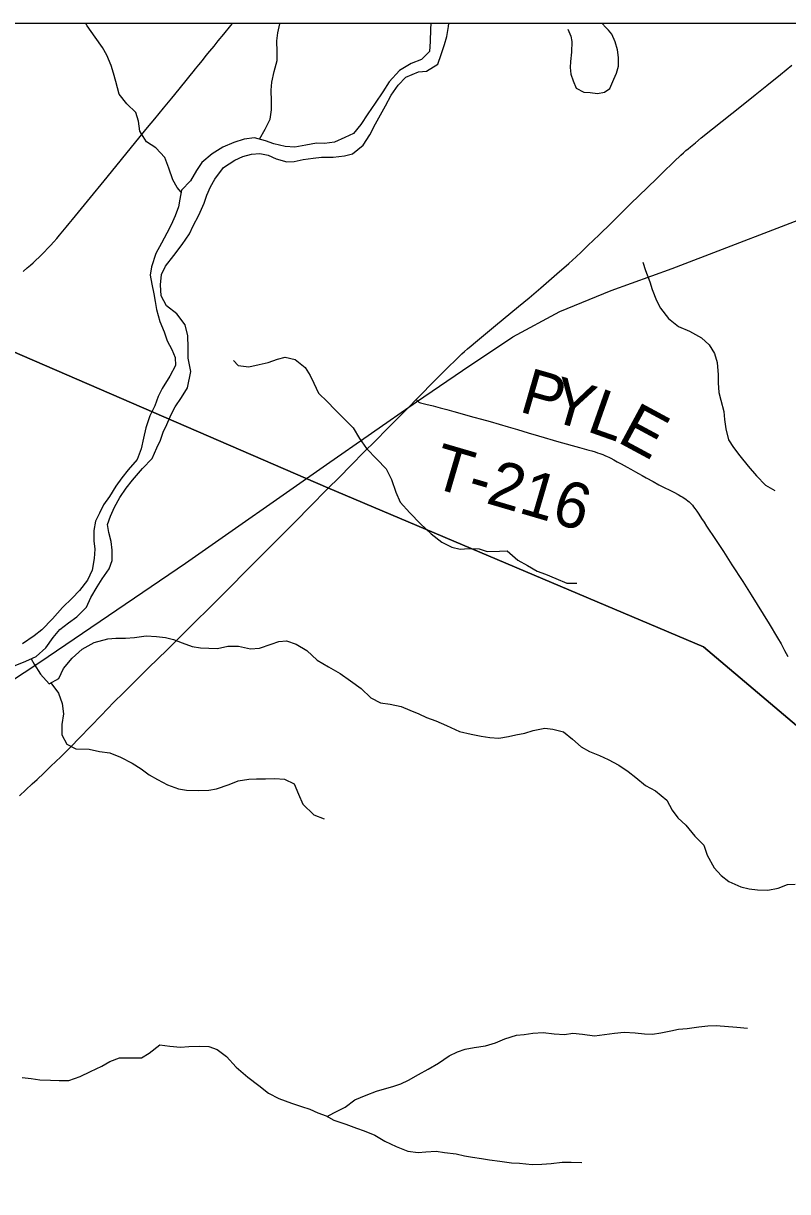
# Model space of a CAD drawing. Extents: x 0 to 34, y 0 to 22.
# Drawn here: x 20.142 to 21.094, y 19.65 to 21.106 of the extents above; entities that cross this region are included whole.
import ezdxf

# ---------------------------------------------------------------- set-up
doc = ezdxf.new("R2010")
doc.units = 0
for name, color, linetype in [('GM_X_Corporation', 7, 'Continuous'), ('GM_X_County_Road', 7, 'Continuous'), ('GM_X_Major_River', 7, 'Continuous'), ('GM_X_Minor_Lake', 7, 'Continuous'), ('GM_X_Minor_River', 7, 'Continuous'), ('GM_X_Rail_Line', 7, 'Continuous'), ('GM_X_Township_Road', 7, 'Continuous'), ('GM_X_Township_Road_Text', 7, 'Continuous')]:
    doc.layers.add(name, color=color, linetype=linetype)

msp = doc.modelspace()

# ---------------------------------------------------------------- linework, layer by layer
at = {"layer": 'GM_X_Corporation'}
for points in [[(17.597, 14.3059), (23.9625, 14.3059), (23.9625, 21.1059), (18.23, 21.1059), (18.203, 20.7746), (18.1731, 20.4696), (18.0879, 19.5959), (18.0387, 19.0962), (17.9672, 18.2605), (17.8718, 17.2256), (17.7834, 16.317), (17.7373, 15.7617), (17.7239, 15.6245), (17.6136, 14.4601)], [(23.8219, 21.1059), (19.1325, 21.1059), (19.4417, 20.9771), (20.0591, 20.7271), (20.5209, 20.5272), (20.9887, 20.3291), (21.1503, 20.1924), (21.2024, 20.1483), (21.462, 19.9289), (21.6862, 19.7442), (22.4736, 19.0897), (22.5453, 19.0171), (22.8523, 19.0143), (22.8728, 18.8666), (23.8372, 18.7818), (23.8567, 18.7798), (23.8401, 19.9225), (23.83, 20.7057)]]:
    msp.add_lwpolyline(points, close=True, dxfattribs=at)
msp.add_lwpolyline([(22.4736, 19.0897), (21.6862, 19.7442), (21.462, 19.9289), (21.2024, 20.1483), (21.1503, 20.1924), (20.9887, 20.3291), (20.5209, 20.5272), (20.0591, 20.7271), (19.4417, 20.9771), (19.1325, 21.1059), (18.23, 21.1059), (18.203, 20.7746), (18.1731, 20.4696), (18.0879, 19.5959), (18.0387, 19.0962), (17.9672, 18.2605), (17.8718, 17.2256), (17.7834, 16.317)], dxfattribs=at)
at = {"layer": 'GM_X_County_Road'}
for points in [[(20.1413, 20.7967), (20.1463, 20.8011), (20.1503, 20.8047), (20.1536, 20.8076), (20.1571, 20.8108), (20.1611, 20.8146), (20.1647, 20.8181), (20.168, 20.8214), (20.1718, 20.8254), (20.1755, 20.8293), (20.1795, 20.8337), (20.1831, 20.8378), (20.1867, 20.8421), (20.1909, 20.8471), (20.1949, 20.8519), (20.1988, 20.8566), (20.2029, 20.8616), (20.2216, 20.8845), (20.2459, 20.9143), (20.2637, 20.9361), (20.2872, 20.9651), (20.2962, 20.9761), (20.3052, 20.987), (20.3162, 21.0003), (20.3265, 21.0127), (20.3357, 21.024), (20.3461, 21.0368), (20.3495, 21.0411), (20.3529, 21.0454), (20.3561, 21.0493), (20.3602, 21.0544), (20.3647, 21.0598), (20.3694, 21.0657), (20.374, 21.0713), (20.3791, 21.0776), (20.3843, 21.0839), (20.3914, 21.0925), (20.4, 21.1033), (20.4021, 21.1059)], [(20.6307, 20.6371), (20.6375, 20.644), (20.65, 20.6566), (20.6609, 20.6675), (20.6696, 20.6761), (20.6814, 20.6878), (20.6878, 20.694), (20.6912, 20.6971), (20.695, 20.7005), (20.6993, 20.7042), (20.7047, 20.7087), (20.7296, 20.7294), (20.7583, 20.7531), (20.7716, 20.764), (20.7861, 20.7763), (20.8063, 20.7938), (20.821, 20.8068), (20.83, 20.815), (20.8364, 20.8208), (20.8445, 20.8285), (20.8524, 20.8362), (20.8583, 20.842), (20.874, 20.8575), (20.8857, 20.8689), (20.8984, 20.8813), (20.9082, 20.8908), (20.9302, 20.9123), (20.9423, 20.9242), (20.9476, 20.9294), (20.9521, 20.9339), (20.9604, 20.9415), (20.9639, 20.9446), (20.9669, 20.9473), (20.9696, 20.9496), (20.9726, 20.9522), (20.9787, 20.9571), (20.9861, 20.9631), (21, 20.9743), (21.0362, 21.0033), (21.0531, 21.0167), (21.0679, 21.0286), (21.0848, 21.0422), (21.099, 21.0536)], [(20.5211, 20.5266), (20.5344, 20.5398), (20.5502, 20.5557), (20.5658, 20.5715), (20.5803, 20.5859), (20.5948, 20.6005), (20.6031, 20.6089), (20.6146, 20.6207), (20.6224, 20.6286), (20.6307, 20.6371)], [(20.1367, 20.1433), (20.1527, 20.1583), (20.1586, 20.1639), (20.1669, 20.1717), (20.1749, 20.1794), (20.1828, 20.187), (20.1873, 20.1914), (20.1943, 20.1982), (20.201, 20.2049), (20.2111, 20.2152), (20.2256, 20.2302), (20.2386, 20.2436), (20.2544, 20.26), (20.2663, 20.2719), (20.2782, 20.284), (20.2975, 20.3028), (20.3208, 20.3255), (20.3406, 20.3451), (20.3578, 20.3623), (20.3705, 20.3749), (20.3829, 20.3872), (20.3925, 20.3969), (20.4011, 20.4056), (20.4162, 20.4207), (20.4437, 20.4484), (20.4819, 20.4867), (20.4978, 20.5027), (20.5211, 20.5266)]]:
    msp.add_lwpolyline(points, dxfattribs=at)
at = {"layer": 'GM_X_Major_River'}
msp.add_line((20.3503, 20.6722), (20.3467, 20.6886), dxfattribs=at)
for points in [[(20.6491, 21.1059), (20.6486, 21.0988), (20.6485, 21.0832), (20.6474, 21.0707), (20.6376, 21.0608), (20.6246, 21.0558), (20.61, 21.0471), (20.5971, 21.033), (20.5892, 21.0207), (20.58, 21.0066), (20.5706, 20.9932), (20.5618, 20.9797), (20.5528, 20.9686), (20.5421, 20.9636), (20.529, 20.9579), (20.5169, 20.9563), (20.5066, 20.9566), (20.4933, 20.9543), (20.4796, 20.9517), (20.4675, 20.9524), (20.4536, 20.9558), (20.4431, 20.9595), (20.4296, 20.9633), (20.4166, 20.9614), (20.4036, 20.9576), (20.3902, 20.9515), (20.3767, 20.9435), (20.3639, 20.9325), (20.3572, 20.9224), (20.3496, 20.9097), (20.3387, 20.8979), (20.3365, 20.8869), (20.3347, 20.8771), (20.3306, 20.8662), (20.3257, 20.855), (20.3205, 20.8445), (20.3137, 20.8322), (20.3065, 20.8191), (20.3011, 20.8025), (20.2997, 20.792), (20.3016, 20.7809), (20.3039, 20.7691), (20.3056, 20.7595), (20.3075, 20.7492), (20.3117, 20.7343), (20.317, 20.7217), (20.3208, 20.7105), (20.3266, 20.6994), (20.3308, 20.6894), (20.3309, 20.6795), (20.3241, 20.6664), (20.3146, 20.6508), (20.3094, 20.641), (20.3053, 20.6294), (20.2992, 20.6167), (20.2942, 20.602), (20.2912, 20.5892), (20.2882, 20.5756), (20.2833, 20.5625), (20.2723, 20.5495), (20.2641, 20.5398), (20.2569, 20.5294), (20.249, 20.5164), (20.2415, 20.5059), (20.2363, 20.4955), (20.2315, 20.4857), (20.2292, 20.474), (20.2292, 20.4611), (20.2305, 20.4508), (20.2297, 20.4391), (20.2271, 20.4248), (20.2214, 20.412), (20.2116, 20.3994), (20.2022, 20.3898), (20.1905, 20.3783), (20.178, 20.3639), (20.1647, 20.3502)], [(20.3467, 20.6886), (20.3467, 20.7022), (20.3464, 20.7167), (20.343, 20.7304), (20.3328, 20.744), (20.3198, 20.7538), (20.3133, 20.7662), (20.3126, 20.7802), (20.3137, 20.7931), (20.3185, 20.8032), (20.3292, 20.8166), (20.3394, 20.8303), (20.3485, 20.8437), (20.3533, 20.8538), (20.3601, 20.8669), (20.3666, 20.8819), (20.3703, 20.8917), (20.3748, 20.9022), (20.38, 20.9119), (20.391, 20.9264), (20.4049, 20.9355), (20.4149, 20.9398), (20.4259, 20.9429), (20.4362, 20.9438), (20.4464, 20.9416), (20.4565, 20.9371), (20.4696, 20.9333), (20.4791, 20.9338), (20.4901, 20.9362), (20.5027, 20.9381), (20.513, 20.939), (20.5274, 20.9393), (20.5418, 20.9408), (20.5517, 20.9432), (20.5649, 20.9542), (20.5732, 20.9669), (20.5804, 20.9808), (20.5864, 20.992), (20.5928, 21.0032), (20.5996, 21.0166), (20.6083, 21.0289), (20.6181, 21.0389), (20.6338, 21.0453), (20.6437, 21.0465), (20.6579, 21.0549), (20.6621, 21.0669), (20.6662, 21.0797), (20.6691, 21.0895), (20.671, 21.1019), (20.6715, 21.1059)], [(20.1312, 20.306), (20.1447, 20.3113), (20.1577, 20.317), (20.1697, 20.3277), (20.1788, 20.3407), (20.1871, 20.3507), (20.1979, 20.3592), (20.208, 20.3665), (20.2201, 20.3787), (20.2257, 20.3907), (20.2337, 20.4037), (20.2396, 20.4138), (20.2483, 20.4261), (20.2524, 20.4366), (20.252, 20.4495), (20.2508, 20.4602), (20.2481, 20.4716), (20.2465, 20.4815), (20.2502, 20.492), (20.2551, 20.5029), (20.2618, 20.5152), (20.2698, 20.5268), (20.2776, 20.5368), (20.2898, 20.5513), (20.3019, 20.5638), (20.3079, 20.577), (20.3124, 20.5867), (20.3157, 20.5965), (20.3201, 20.6062), (20.3258, 20.6186), (20.3306, 20.6283), (20.3385, 20.6399), (20.346, 20.6518), (20.3503, 20.6722)], [(20.1647, 20.3502), (20.155, 20.3429), (20.1407, 20.3327)]]:
    msp.add_lwpolyline(points, dxfattribs=at)
at = {"layer": 'GM_X_Minor_Lake'}
for points in [[(20.8704, 21.0972), (20.8672, 21.1008), (20.8626, 21.1059)], [(20.8198, 21.0987), (20.8234, 21.0899), (20.8248, 21.0831), (20.8245, 21.0698), (20.8231, 21.0585), (20.8226, 21.0509), (20.8236, 21.0425), (20.8264, 21.0341), (20.83, 21.0253), (20.8398, 21.0202), (20.8477, 21.0196), (20.8568, 21.0183), (20.8655, 21.02), (20.8721, 21.0249), (20.8769, 21.0365), (20.8804, 21.044), (20.8829, 21.0527), (20.8831, 21.0633), (20.8818, 21.0729), (20.8789, 21.0828), (20.8746, 21.0924), (20.8704, 21.0972)]]:
    msp.add_lwpolyline(points, dxfattribs=at)
at = {"layer": 'GM_X_Minor_River'}
for points in [[(20.3382, 20.8955), (20.3331, 20.9015), (20.3276, 20.9111), (20.3226, 20.9253), (20.3176, 20.9386), (20.3065, 20.9506), (20.2949, 20.9581), (20.2868, 20.9715), (20.2848, 20.9841), (20.2816, 20.9948), (20.2705, 21.0056), (20.2608, 21.0176), (20.2566, 21.0336), (20.2538, 21.0439), (20.251, 21.0534), (20.2455, 21.0661), (20.2401, 21.0757), (20.2309, 21.0887), (20.2209, 21.103), (20.2195, 21.1059)], [(20.4357, 20.9616), (20.4429, 20.9741), (20.4489, 20.9865), (20.4506, 20.9983), (20.4505, 21.0089), (20.4504, 21.0226), (20.451, 21.0328), (20.4539, 21.046), (20.4579, 21.0596), (20.4578, 21.0702), (20.4573, 21.0843), (20.4586, 21.0941), (20.4611, 21.1051), (20.4616, 21.1059)], [(20.9133, 20.8085), (20.9167, 20.7978), (20.9221, 20.784), (20.9249, 20.7745), (20.9303, 20.7607), (20.9354, 20.7511), (20.945, 20.738), (20.9577, 20.7283), (20.9712, 20.7223), (20.9862, 20.7141), (20.9959, 20.7055), (21.0025, 20.6944), (21.0057, 20.6833), (21.0072, 20.6678), (21.007, 20.6579), (21.0079, 20.6461), (21.0104, 20.6366), (21.0143, 20.6221), (21.0148, 20.6122), (21.0165, 20.6008), (21.02, 20.5871), (21.0262, 20.5774), (21.034, 20.567), (21.0443, 20.5543), (21.0547, 20.542), (21.0662, 20.5307), (21.0778, 20.5237)], [(20.4032, 20.6859), (20.4093, 20.6796), (20.4225, 20.6778), (20.4355, 20.6809), (20.4465, 20.6834), (20.4583, 20.6873), (20.4678, 20.6898), (20.4803, 20.6869), (20.4926, 20.6771), (20.4988, 20.6672), (20.5032, 20.6576), (20.5094, 20.6453), (20.5205, 20.6345), (20.5294, 20.6248), (20.5424, 20.612), (20.5524, 20.602), (20.5601, 20.5885), (20.5689, 20.5762), (20.5819, 20.5631), (20.5934, 20.5507), (20.6, 20.5377), (20.6057, 20.5216), (20.6108, 20.5094), (20.623, 20.4962), (20.6364, 20.4823), (20.6494, 20.4699), (20.6628, 20.4594), (20.6752, 20.4531), (20.6857, 20.4506), (20.6963, 20.4515), (20.7092, 20.4513), (20.7194, 20.448), (20.7345, 20.4481), (20.7444, 20.4487), (20.7574, 20.437), (20.7694, 20.4304), (20.7818, 20.4233), (20.7919, 20.4197), (20.8047, 20.4141), (20.8186, 20.4085), (20.8311, 20.4083)], [(20.1513, 20.3142), (20.1551, 20.3074), (20.1631, 20.2951), (20.1739, 20.2831), (20.1858, 20.2897), (20.1917, 20.3021), (20.2022, 20.3148), (20.2149, 20.3263), (20.2299, 20.3347), (20.247, 20.339), (20.2569, 20.3399), (20.2686, 20.34), (20.28, 20.3406), (20.2944, 20.3426), (20.3073, 20.3419), (20.3186, 20.3406), (20.3288, 20.3381), (20.3393, 20.3341), (20.3518, 20.3297), (20.3623, 20.328), (20.3725, 20.3274), (20.3832, 20.3272), (20.3961, 20.3299), (20.4097, 20.3301), (20.4244, 20.3267), (20.4358, 20.3273), (20.4503, 20.3323), (20.4599, 20.3359), (20.4693, 20.3365), (20.4814, 20.3324), (20.4945, 20.3246), (20.5075, 20.3126), (20.5217, 20.3043), (20.5363, 20.2957), (20.549, 20.2867), (20.5625, 20.2773), (20.5743, 20.2657), (20.5863, 20.2594), (20.5984, 20.2577), (20.612, 20.2547), (20.6229, 20.25), (20.6342, 20.2456), (20.6439, 20.2412), (20.6552, 20.2368), (20.6687, 20.2309), (20.6849, 20.2237), (20.6992, 20.2204), (20.712, 20.2179), (20.7226, 20.2161), (20.7339, 20.2155), (20.7457, 20.2172), (20.7552, 20.2193), (20.7663, 20.2217), (20.7766, 20.2249), (20.791, 20.2277), (20.8012, 20.2267), (20.8144, 20.223), (20.8256, 20.2141), (20.8364, 20.2044), (20.8469, 20.1985), (20.8593, 20.1937), (20.8702, 20.1889), (20.8833, 20.1815), (20.8949, 20.1737), (20.9046, 20.1663), (20.9165, 20.1565), (20.9292, 20.1498), (20.943, 20.1382), (20.9499, 20.1255), (20.9569, 20.1159), (20.9666, 20.107), (20.9781, 20.0931), (20.9892, 20.0819), (20.9935, 20.0696), (21.0019, 20.0539), (21.0108, 20.0443), (21.0205, 20.0369), (21.0355, 20.0301), (21.0457, 20.0276), (21.0559, 20.0263), (21.0688, 20.026), (21.0817, 20.0284), (21.0935, 20.0328), (21.103, 20.0333)], [(20.176, 20.2843), (20.1854, 20.2715), (20.1901, 20.2585), (20.1917, 20.2456), (20.1895, 20.2323), (20.1896, 20.2194), (20.1958, 20.2079), (20.2071, 20.202), (20.2237, 20.2017), (20.2366, 20.1988), (20.2494, 20.197), (20.2626, 20.1918), (20.2772, 20.1843), (20.2884, 20.1769), (20.2981, 20.1695), (20.3086, 20.164), (20.3213, 20.1573), (20.3349, 20.1521), (20.3447, 20.1507), (20.3602, 20.15), (20.3727, 20.1505), (20.3822, 20.1523), (20.3979, 20.1576), (20.4093, 20.162), (20.4223, 20.1644), (20.4321, 20.1646), (20.4431, 20.1647), (20.4549, 20.1652), (20.467, 20.1642), (20.479, 20.1583), (20.4844, 20.1457), (20.4898, 20.1331), (20.5032, 20.1199), (20.5163, 20.1147)], [(20.5202, 19.7438), (20.5285, 19.7487), (20.5423, 19.7556), (20.5546, 19.7649), (20.5688, 19.7707), (20.5814, 19.7754), (20.5913, 19.7786), (20.6019, 19.7814), (20.6119, 19.7846), (20.6214, 19.7894), (20.6337, 19.7963), (20.6459, 19.8029), (20.6586, 19.8103), (20.672, 19.8195), (20.6824, 19.8246), (20.6919, 19.8278), (20.7033, 19.8299), (20.7174, 19.8319), (20.7296, 19.8358), (20.7414, 19.8409), (20.7559, 19.8451), (20.7654, 19.8461), (20.7764, 19.8478), (20.789, 19.8487), (20.8029, 19.8469), (20.8158, 19.8462), (20.8261, 19.8476), (20.8382, 19.8466), (20.8529, 19.8444), (20.8654, 19.846), (20.878, 19.8477), (20.8901, 19.849), (20.9037, 19.8483), (20.9155, 19.8469), (20.9253, 19.8464), (20.9356, 19.8481), (20.9481, 19.8508), (20.9576, 19.8529), (20.9686, 19.8535), (20.9831, 19.8558), (20.9941, 19.8571), (21.0047, 19.8573), (21.0304, 19.8553), (21.0436, 19.8539)], [(20.14, 19.7924), (20.1513, 19.7914), (20.1623, 19.7897), (20.1755, 19.7894), (20.1861, 19.7888), (20.1982, 19.7886), (20.2124, 19.7936), (20.2254, 19.8002), (20.2395, 19.8067), (20.2491, 19.8126), (20.2613, 19.8169), (20.2761, 19.817), (20.2886, 19.8172), (20.2982, 19.823), (20.3117, 19.8334), (20.3241, 19.8316), (20.3374, 19.8302), (20.3476, 19.8312), (20.3609, 19.8317), (20.3726, 19.8311), (20.3828, 19.8275), (20.3947, 19.8185), (20.4066, 19.8054), (20.4211, 19.7929), (20.4349, 19.7824), (20.4468, 19.7731), (20.4599, 19.7664), (20.4754, 19.7604), (20.4882, 19.7563), (20.4983, 19.7531), (20.5085, 19.7487), (20.5186, 19.7447), (20.5283, 19.7392), (20.5434, 19.7344), (20.5566, 19.7296), (20.5663, 19.7259), (20.5795, 19.7208), (20.5918, 19.7133), (20.6061, 19.7066), (20.6204, 19.7006), (20.6332, 19.6992), (20.6431, 19.6998), (20.6556, 19.7007), (20.6662, 19.6989), (20.6809, 19.6975), (20.6911, 19.695), (20.7009, 19.6933), (20.7122, 19.6916), (20.7221, 19.6899), (20.7349, 19.6885), (20.7496, 19.6863), (20.7595, 19.6857), (20.7754, 19.6843), (20.7875, 19.6844), (20.7989, 19.6853), (20.8129, 19.6869), (20.8239, 19.6871), (20.8372, 19.6865)]]:
    msp.add_lwpolyline(points, dxfattribs=at)
at = {"layer": 'GM_X_Rail_Line'}
msp.add_lwpolyline([(19.9408, 20.1642), (20.1621, 20.3101), (20.3436, 20.4332), (20.5192, 20.5564), (20.6312, 20.6343), (20.6884, 20.6735), (20.7515, 20.7155), (20.8098, 20.747), (20.8739, 20.773), (20.9497, 20.8005), (21.1487, 20.8768), (21.283, 20.9317), (21.346, 20.9515), (21.4058, 20.964), (21.4578, 20.9704), (21.5362, 20.9801), (21.65, 20.986), (21.8845, 21.0002)], dxfattribs=at)
at = {"layer": 'GM_X_Township_Road'}
msp.add_lwpolyline([(20.6307, 20.6371), (20.6328, 20.6352), (20.6336, 20.6345), (20.6343, 20.634), (20.6351, 20.6335), (20.6363, 20.6331), (20.6429, 20.6315), (20.6522, 20.6292), (20.6609, 20.6269), (20.6692, 20.6247), (20.6776, 20.6224), (20.6882, 20.6195), (20.6953, 20.6175), (20.7027, 20.6154), (20.7124, 20.6126), (20.7229, 20.6097), (20.7342, 20.6065), (20.7453, 20.6032), (20.7573, 20.5997), (20.7706, 20.5958), (20.7832, 20.5921), (20.8085, 20.5847), (20.8343, 20.5774), (20.8461, 20.5742), (20.8499, 20.5732), (20.8537, 20.572), (20.8569, 20.571), (20.8597, 20.57), (20.8632, 20.5686), (20.866, 20.5674), (20.8688, 20.5662), (20.871, 20.5652), (20.8734, 20.564), (20.8771, 20.5621), (20.8814, 20.5597), (20.8861, 20.5572), (20.89, 20.5551), (20.8936, 20.553), (20.8984, 20.5503), (20.9041, 20.547), (20.9079, 20.5449), (20.9124, 20.5424), (20.9175, 20.5396), (20.9259, 20.535), (20.9333, 20.5311), (20.9406, 20.5273), (20.9459, 20.5246), (20.9519, 20.5216), (20.9573, 20.5188), (20.9606, 20.517), (20.9624, 20.5159), (20.9643, 20.5147), (20.9671, 20.5128), (20.9693, 20.511), (20.971, 20.5096), (20.9727, 20.5079), (20.9738, 20.5067), (20.975, 20.5054), (20.9763, 20.5036), (20.978, 20.5013), (20.9804, 20.4981), (20.983, 20.4942), (20.9865, 20.4891), (20.9895, 20.4844), (20.9927, 20.4796), (21.0037, 20.4629), (21.0138, 20.4478), (21.0243, 20.4314), (21.0377, 20.4106), (21.0483, 20.3938), (21.0705, 20.3579), (21.0811, 20.3403), (21.0854, 20.3328), (21.0899, 20.3246), (21.0939, 20.3169)], dxfattribs=at)

# ---------------------------------------------------------------- texts
at = {"layer": 'GM_X_Township_Road_Text'}
for s, height, rotation, p in [('P', 0.0568, 343.9202, (20.7578, 20.6226)), ('Y', 0.0568, 343.8535, (20.7946, 20.612)), ('L', 0.0568, 340.5764, (20.8418, 20.5983)), ('E', 0.0568, 331.6628, (20.8798, 20.5852)), ('T-216', 0.05682, 343.6407, (20.6475, 20.5288))]:
    msp.add_text(s, height=height, rotation=rotation, dxfattribs=at).set_placement(p)

doc.saveas('drawing.dxf')
